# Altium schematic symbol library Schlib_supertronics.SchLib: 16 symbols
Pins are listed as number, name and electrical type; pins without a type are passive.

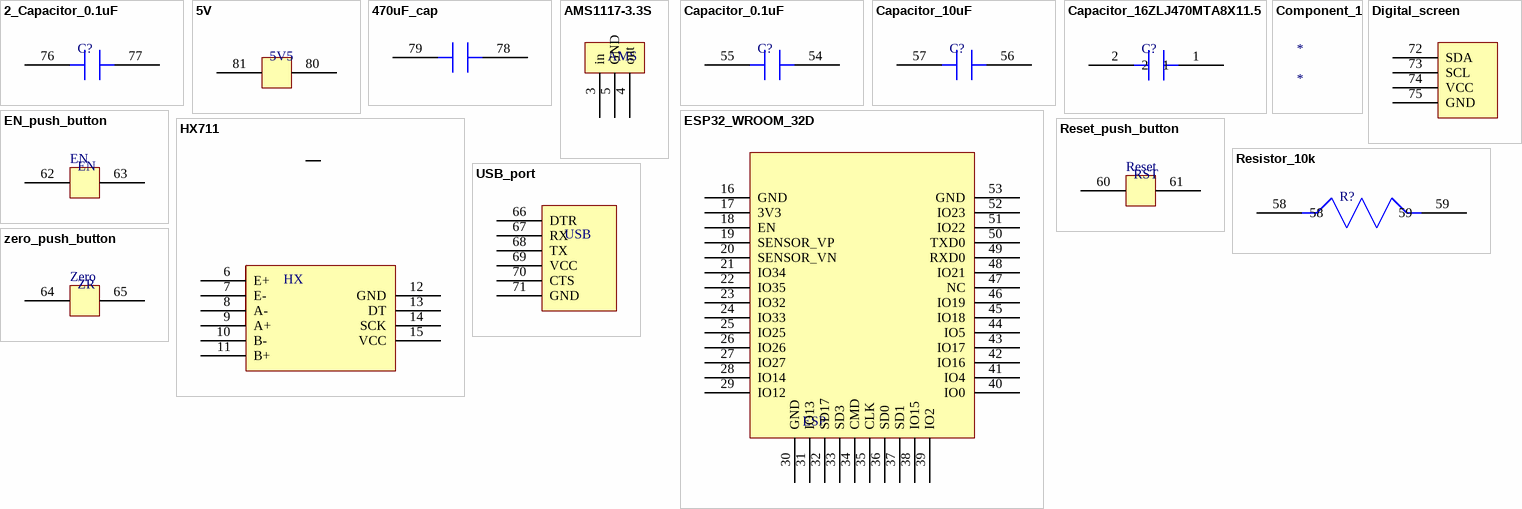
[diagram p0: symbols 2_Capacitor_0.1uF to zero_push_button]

## 2_Capacitor_0.1uF
designator C?
footprint 0.1uF_Capacitor
pins: 76, 77

## 5V
designator 5V5
footprint 5V5
pins: 80, 81

## 470uF_cap
designator C?
470 µF 16 V Aluminum Electrolytic Capacitors Radial, Can 9000 Hrs @ 105°C
footprint 470uF_Capacitor (470 µF 16 V Aluminum Electrolytic Capacitors Radial, Can 9000 Hrs @ 105°C)
pins: 78, 79

## AMS1117-3.3S
designator AMS
Linear Voltage Regulator IC Positive Fixed 1 Output 1A SOT-89
footprint AMS1117-3.3s
pins: 3 in, 4 out, 5 GND

## Capacitor_0.1uF
designator C?
0.1uF
footprint Cap_0.1uF
pins: 54, 55

## Capacitor_10uF
designator C?
10uF
footprint 10uF_Capacitor
pins: 56,  57

## Capacitor_16ZLJ470MTA8X11.5
designator C?
470 µF 16 V Aluminum Electrolytic Capacitors Radial, Can 9000 Hrs @ 105°C
footprint Cap_470_16z
pins: 1, 2

## Component_1
designator *

## Digital_screen
designator DS
footprint Digital_screen (Screen)
pins: 72 SDA, 73 SCL, 74 VCC, 75 GND

## EN_push_button
designator EN
EN
footprint EN_push_button (EN)
pins: 62, 63

## ESP32_WROOM_32D
designator ESP
footprint ESP32_WROOM32D
pins: 16 GND, 17 3V3, 18 EN, 19 SENSOR_VP, 20 SENSOR_VN, 21 IO34, 22 IO35, 23 IO32, 24 IO33, 25 IO25, 26 IO26, 27 IO27, 28 IO14, 29 IO12, 30 GND, 31 IO13, 32 SD17, 33 SD3, 34 CMD, 35 CLK, 36 SD0, 37 SD1, 38 IO15, 39 IO2, 40 IO0, 41 IO4, 42 IO16, 43 IO17, 44 IO5, 45 IO18, 46 IO19, 47 NC, 48 IO21, 49 RXD0, 50 TXD0, 51 IO22, 52 IO23, 53 GND

## HX711
designator HX
footprint HX711
pins: 6 E+, 7 E-, 8 A-, 9 A+, 10 B-, 11 B+, 12 GND, 13 DT, 14 SCK, 15 VCC

## Reset_push_button
designator RST
Reset
footprint Reset_push_button (Reset)
pins: 60, 61

## Resistor_10k
designator R?
10kOhm
footprint 10K_ohm_resistor (Resistor)
pins: 58, 59

## USB_port
designator USB
footprint USB_port (USB)
pins: 66 DTR, 67 RX, 68 TX, 69 VCC, 70 CTS, 71 GND

## zero_push_button
designator ZR
Zero
footprint Zero_push_button (Zero)
pins: 64, 65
